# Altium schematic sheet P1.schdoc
size 297 x 209 mm; Symbol: Drawing-Symbol_A4; Company: 嘉立创EDA; Version: V1.0; Page Size: A4; @Project Name: New Project_2025-04-26_14-25-05; @Page Count: 1; @Update Date: 2025-05-09; @Create Date: 2025-04-26; @Schematic Name: Schematic1; @Page No: 1; @Page Name: P1; @Create Time: 14:25:06; @Update Time: 19:43:00; Border: 1; Width: 1170; Height: 825; Region Start: 1; X Region Count: 6; Y Region Count: 4; Blade Width: 10; Title Block Position: 3; @Board Name: 小车板子; Device: Drawing-Symbol_A4
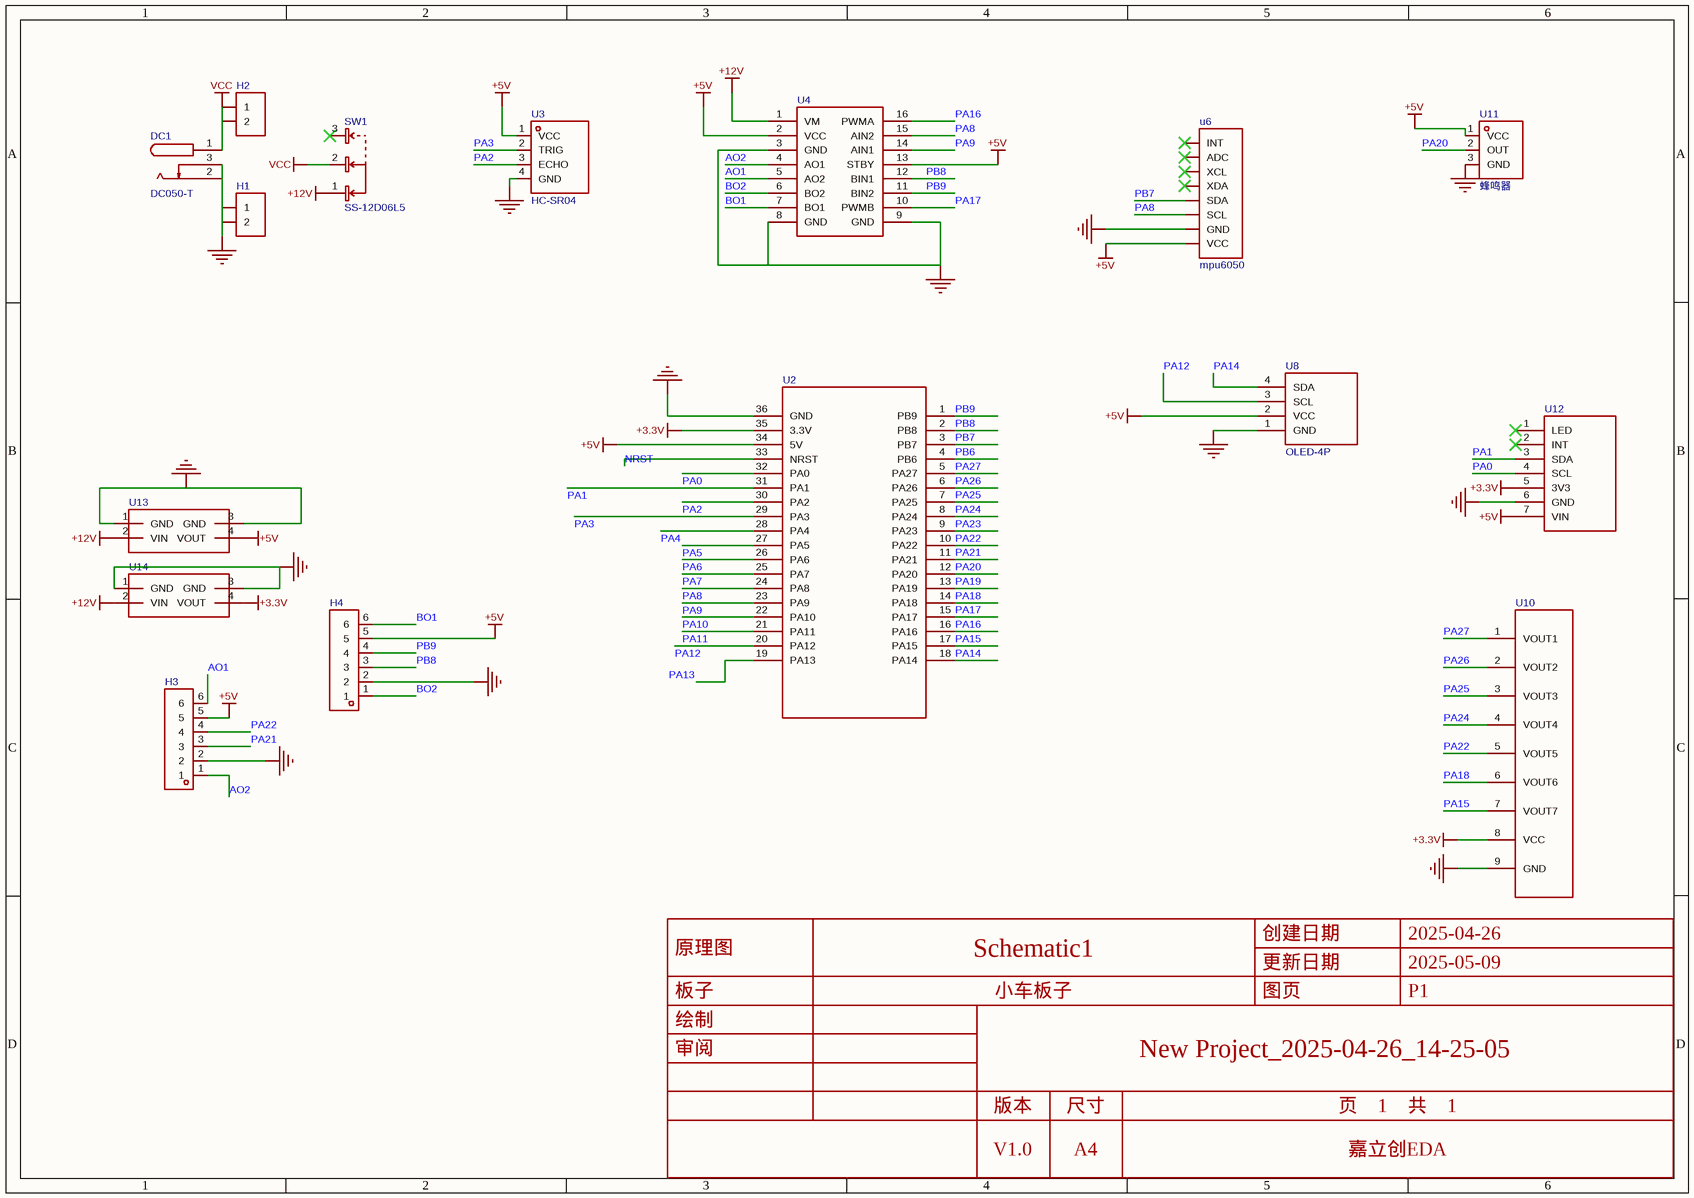
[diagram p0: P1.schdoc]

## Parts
DC1  DC050-T  [DC-IN_DC050-T]
H1  (no value)  [HDR-TH_2P-P2.54-V-F]
H2  (no value)  [HDR-TH_2P-P2.54-V-F]
H3  (no value)  [HDR-TH_6P-P2.54-V-F]
H4  (no value)  [HDR-TH_6P-P2.54-V-F]
SW1  SS-12D06L5  [SW-TH_3P-P4.70_L11.1-W12.7]
U2  (no value)  [5307]
U3  HC-SR04  [HC-SR04]
U4  (no value)  [TB6612]
u6  mpu6050  [MPU6050模块]
U8  OLED-4P  [HDR-TH_4P-P2.54-V-F]
U10  (no value)  [huidu]
U11  蜂鸣器  [蜂鸣器]
U12  (no value)  [tcs34725]
U13  (no value)  [MP2236]
U14  (no value)  [MP2236]

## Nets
+3.3V: U2.35(3.3V) U10.8(VCC) U12.5(3V3) U14.4(VOUT)
+5V: H3.5 H4.5 U2.34(5V) U3.1(VCC) U4.2(VCC) U4.13(STBY) u6.VCC U8.2(VCC) U11.1(VCC) U12.7(VIN) U13.4(VOUT)
+12V: SW1.1 U4.1(VM) U13.2(VIN) U14.2(VIN)
GND: DC1.2 DC1.3 H1.1 H1.2 H3.2 H4.2 U2.36(GND) U3.4(GND) U4.3(GND) U4.8(GND) U4.9(GND) u6.GND U8.1(GND) U10.9(GND) U11.3(GND) U12.6(GND) U13.1(GND) U13.3(GND) U14.1(GND) U14.3(GND)
VCC: DC1.1 H2.1 H2.2 SW1.2
AO1: H3.6 U4.5(AO2)
AO2: H3.1 U4.4(AO1)
BO1: H4.6 U4.7(BO1)
BO2: H4.1 U4.6(BO2)
NRST: U2.33(NRST)
PA0: U2.32(PA0) U12.4(SCL)
PA1: U2.31(PA1) U12.3(SDA)
PA2: U2.30(PA2) U3.3(ECHO)
PA3: U2.29(PA3) U3.2(TRIG)
PA4: U2.28(PA4)
PA5: U2.27(PA5)
PA6: U2.26(PA6)
PA7: U2.25(PA7)
PA8: U2.24(PA8) U4.15(AIN2) u6.SCL
PA9: U2.23(PA9) U4.14(AIN1)
PA10: U2.22(PA10)
PA11: U2.21(PA11)
PA12: U2.20(PA12) U8.3(SCL)
PA13: U2.19(PA13)
PA14: U2.18(PA14) U8.4(SDA)
PA15: U2.17(PA15) U10.7(VOUT7)
PA16: U2.16(PA16) U4.16(PWMA)
PA17: U2.15(PA17) U4.10(PWMB)
PA18: U2.14(PA18) U10.6(VOUT6)
PA19: U2.13(PA19)
PA20: U2.12(PA20) U11.2(OUT)
PA21: H3.3 U2.11(PA21)
PA22: H3.4 U2.10(PA22) U10.5(VOUT5)
PA23: U2.9(PA23)
PA24: U2.8(PA24) U10.4(VOUT4)
PA25: U2.7(PA25) U10.3(VOUT3)
PA26: U2.6(PA26) U10.2(VOUT2)
PA27: U2.5(PA27) U10.1(VOUT1)
PB6: U2.4(PB6)
PB7: U2.3(PB7) u6.SDA
PB8: H4.3 U2.2(PB8) U4.12(BIN1)
PB9: H4.4 U2.1(PB9) U4.11(BIN2)

Not connected (* = marked no-connect by the designer): SW1 3*; u6 ADC* INT* XCL* XDA*; U12 1(LED)* 2(INT)*

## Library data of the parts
DC1 = DC050-T: 连接器类型:DC电源插座;安装方式:卧贴;触点内径:2mm;触点外径:6.4mm;额定电流:2A;额定电压:30V;工作温度范围:-25℃~+70℃;; Manufacturer: SHOU HAN(首韩); AddInBom: yes; ModelId: 142cce1c07ad45eeb3b16ff7da67335b; ModelTransform: 582.676,511.81,0,0,0,0,-18.475,-11.207,-27.559; Connector Type: DC电源插座; Inside Contact Diameter: 2mm; Outside Contact Diameter: 6.4mm; Current Rating (Max): 2A; Voltage Rating (Max): 30V
H1 H2 = HDR-F_2.54_1x2P: Symbol: Header-Female-2.54_1x2; ConvertToPcb: yes; ModelId: a9450ef445564560a104363b9aacde4e; ModelName: HDR-TH_2P-P2.54-F-LI-1X2P; ModelTransform: 215.7476,98.425,0,0,0,0,0,0,-129.921
H3 H4 = HDR-F_2.54_1x6P: Symbol: Header-Female-2.54_1x6; ConvertToPcb: yes; ModelId: 0f5bcf94dcda47d085f24cdca1696fe9; ModelTransform: 619.684,94.488,0,0,0,0,0,0,-125.984
SW1 = SS-12D06L5: 电路结构:单刀双掷;安装方式:侧插;开关颜色:黑色;额定电流(DC):3A;额定电压(DC):250V;额定电流(AC):3A;额定电压(AC):250V;机械寿命:1万次;; Manufacturer: XKB Connectivity(中国星坤); AddInBom: yes; ModelId: cdc951e5f4794e0cacc9ea6ffda3ed7a; ModelTransform: 509.842,582.67596,0,0,0,0,0,-265.748,-145.669; Circuit: 单刀双掷; Actuator Style: 矩形柱状; Pin Style: PC引脚; Switch Length: 12.95mm; Switch Width: 6.6mm; Switch Height: 6.3mm; Actuator Color: 黑色; Current Rating (DC): 3A; Voltage Rating (DC): 250V; Mechanical Life: 1万次
U2 = 嘉立创-MSPM0G3507-核心板: AddInBom: yes
U3 = HC-SR04: Manufacturer: Universal Microelectronics; AddInBom: yes
U4 = TB6612: AddInBom: yes
u6 = MPU6050模块: AddInBom: yes; _: 3
U8 = OLED-4P: 0.91寸,0.96寸，1.3寸 OLED 4Pin 显示屏模块; AddInBom: yes; ModelId: 1e5dda4e40184d7ba66a8784a7df3334user; ModelName: CONN-TH_4P-P2.50_HDGC2512WV-4P; ModelTransform: 492.12,256.3,409.45,0,0,0,0,0,0
U10 = 七路灰度传感器: AddInBom: yes
U11 = 蜂鸣器: AddInBom: yes; ModelId: bb473b6d38ff42a99216a4fcdbdcc4cb; ModelName: HDR-TH_3P-P2.54-M-LI-1X3P; ModelTransform: 299.9994,100,0,0,0,0,0,0,-118.11; SymbolName: 2.54MM间距单排插针3P/高度11MM
U12 = tcs34725: AddInBom: yes
U13 U14 = MP2236: AddInBom: yes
